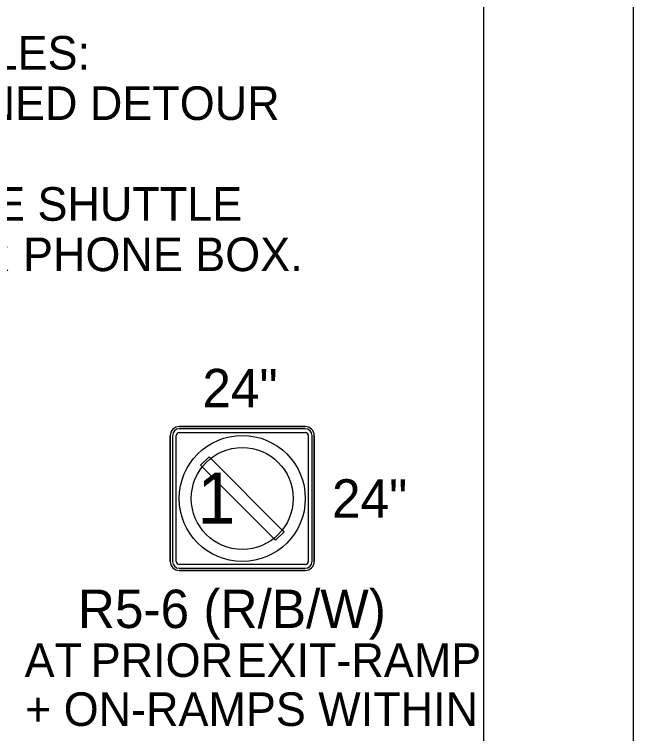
# Model space of a CAD drawing. Extents: x 99999 to 100116, y 99995 to 100013.
# Drawn here: x 100014.772 to 100016.062, y 100001.262 to 100002.761 of the extents above; entities that cross this region are included whole.
import ezdxf

# ---------------------------------------------------------------- set-up
doc = ezdxf.new("R2010")
doc.units = 0
for name, color, linetype in [('SH_GI_GeneralNotesBodyText', 7, 'Continuous'), ('SH_GI_PlotLimits', 7, 'Continuous'), ('SH_GI_SheetBorder', 7, 'Continuous'), ('TR_SN_ConstructionSigns', 7, 'Continuous')]:
    doc.layers.add(name, color=color, linetype=linetype)

msp = doc.modelspace()

# ---------------------------------------------------------------- linework, layer by layer
at = {"layer": 'SH_GI_PlotLimits'}
msp.add_lwpolyline([(99999.0625, 99999.6875), (100016.0625, 99999.6875), (100016.0625, 100010.6875), (99999.0625, 100010.6875)], close=True, dxfattribs=at)
at = {"layer": 'SH_GI_SheetBorder'}
msp.add_line((100015.75, 100010.375), (100015.75, 100000), dxfattribs=at)
at = {"layer": 'TR_SN_ConstructionSigns'}
for p, q in [((100015.3783, 100001.9019), (100015.1158, 100001.9019)), ((100015.1158, 100001.9019), (100015.3783, 100001.9019)), ((100015.3783, 100001.9019), (100015.1158, 100001.9019)), ((100015.3783, 100001.8972), (100015.1158, 100001.8972)), ((100015.1158, 100001.8894), (100015.3783, 100001.8894)), ((100015.0971, 100001.8831), (100015.0971, 100001.6206)), ((100015.0971, 100001.6206), (100015.0971, 100001.8831)), ((100015.0971, 100001.8831), (100015.0971, 100001.6206)), ((100015.1018, 100001.8831), (100015.1018, 100001.6206)), ((100015.1096, 100001.6206), (100015.1096, 100001.8831)), ((100015.3846, 100001.8831), (100015.3846, 100001.6206)), ((100015.3924, 100001.6206), (100015.3924, 100001.8831)), ((100015.3971, 100001.6206), (100015.3971, 100001.8831)), ((100015.3971, 100001.8831), (100015.3971, 100001.6206)), ((100015.3971, 100001.6206), (100015.3971, 100001.8831)), ((100015.3783, 100001.6144), (100015.1158, 100001.6144)), ((100015.1158, 100001.6066), (100015.3783, 100001.6066)), ((100015.1158, 100001.6019), (100015.3783, 100001.6019)), ((100015.3783, 100001.6019), (100015.1158, 100001.6019)), ((100015.1158, 100001.6019), (100015.3783, 100001.6019))]:
    msp.add_line(p, q, dxfattribs=at)
msp.add_lwpolyline([(100015.3305, 100001.6861), (100015.1813, 100001.8353), (100015.1778, 100001.8389), (100015.1601, 100001.8212), (100015.3128, 100001.6685), (100015.3164, 100001.6649), (100015.3341, 100001.6826), (100015.3305, 100001.6861)], dxfattribs=at)
for radius in [0.1313, 0.1062]:
    msp.add_circle((100015.2471, 100001.7519), radius, dxfattribs=at)
for centre, radius, start, end in [((100015.1158, 100001.8831), 0.0187, 90, 180), ((100015.1158, 100001.8831), 0.0187, 90, 180), ((100015.1158, 100001.8831), 0.0187, 90, 180), ((100015.3783, 100001.8831), 0.0187, 0, 90), ((100015.3783, 100001.8831), 0.0187, 0, 90), ((100015.3783, 100001.8831), 0.0187, 0, 90), ((100015.1158, 100001.8831), 0.0141, 90, 180), ((100015.1158, 100001.8831), 0.00625, 90, 180), ((100015.3783, 100001.8831), 0.0141, 0, 90), ((100015.3783, 100001.8831), 0.00625, 0, 90), ((100015.1158, 100001.6206), 0.0187, 180, 270), ((100015.1158, 100001.6206), 0.0187, 180, 270), ((100015.1158, 100001.6206), 0.0187, 180, 270), ((100015.1158, 100001.6206), 0.0141, 180, 270), ((100015.1158, 100001.6206), 0.00625, 180, 270), ((100015.3783, 100001.6206), 0.0141, 270, 0), ((100015.3783, 100001.6206), 0.00625, 270, 0), ((100015.3783, 100001.6206), 0.0187, 270, 0), ((100015.3783, 100001.6206), 0.0187, 270, 0), ((100015.3783, 100001.6206), 0.0187, 270, 0)]:
    msp.add_arc(centre, radius, start, end, dxfattribs=at)

# ---------------------------------------------------------------- texts
at = {"layer": 'SH_GI_GeneralNotesBodyText'}
for s, p in [('11. BICYCLIST ACCOMMODATIONS, WHERE FACILITY OPEN TO BICYCLES:', (100011.549, 100002.6456)), ('(A) BICYCLES PROHIBITED VIA R5-601 & R5-6 SIGNS. PROVIDE SIGNED DETOUR ', (100011.689, 100002.5406)), ('(B) BICYCLES PROHIBITED VIA R5-601 & R5-6 SIGNS. PROVIDE FREE SHUTTLE ', (100011.689, 100002.3306)), ('(WORK TRUCK, VAN, OR BUS OK) + CONTACT INFORMATION OR PHONE BOX.', (100011.839, 100002.2256))]:
    msp.add_text(s, height=0.07, rotation=360, dxfattribs=at).set_placement(p)
at = {"layer": 'TR_SN_ConstructionSigns'}
for s, height, p in [('24"', 0.08, (100015.164, 100001.9419)), ('24"', 0.08, (100015.434, 100001.7119)), ('R5-6 (R/B/W)', 0.08, (100014.9045, 100001.4819)), ('AT', 0.07, (100014.7937, 100001.3799)), ('PRIOR', 0.07, (100014.9314, 100001.3799)), ('EXIT-RAMP', 0.07, (100015.2353, 100001.3799)), ('+ ON-RAMPS WITHIN', 0.07, (100014.7944, 100001.2779))]:
    msp.add_text(s, height=height, rotation=360, dxfattribs=at).set_placement(p)
msp.add_text('1', height=0.1065, dxfattribs=at).set_placement((100015.1538, 100001.6994))

doc.saveas('drawing.dxf')
